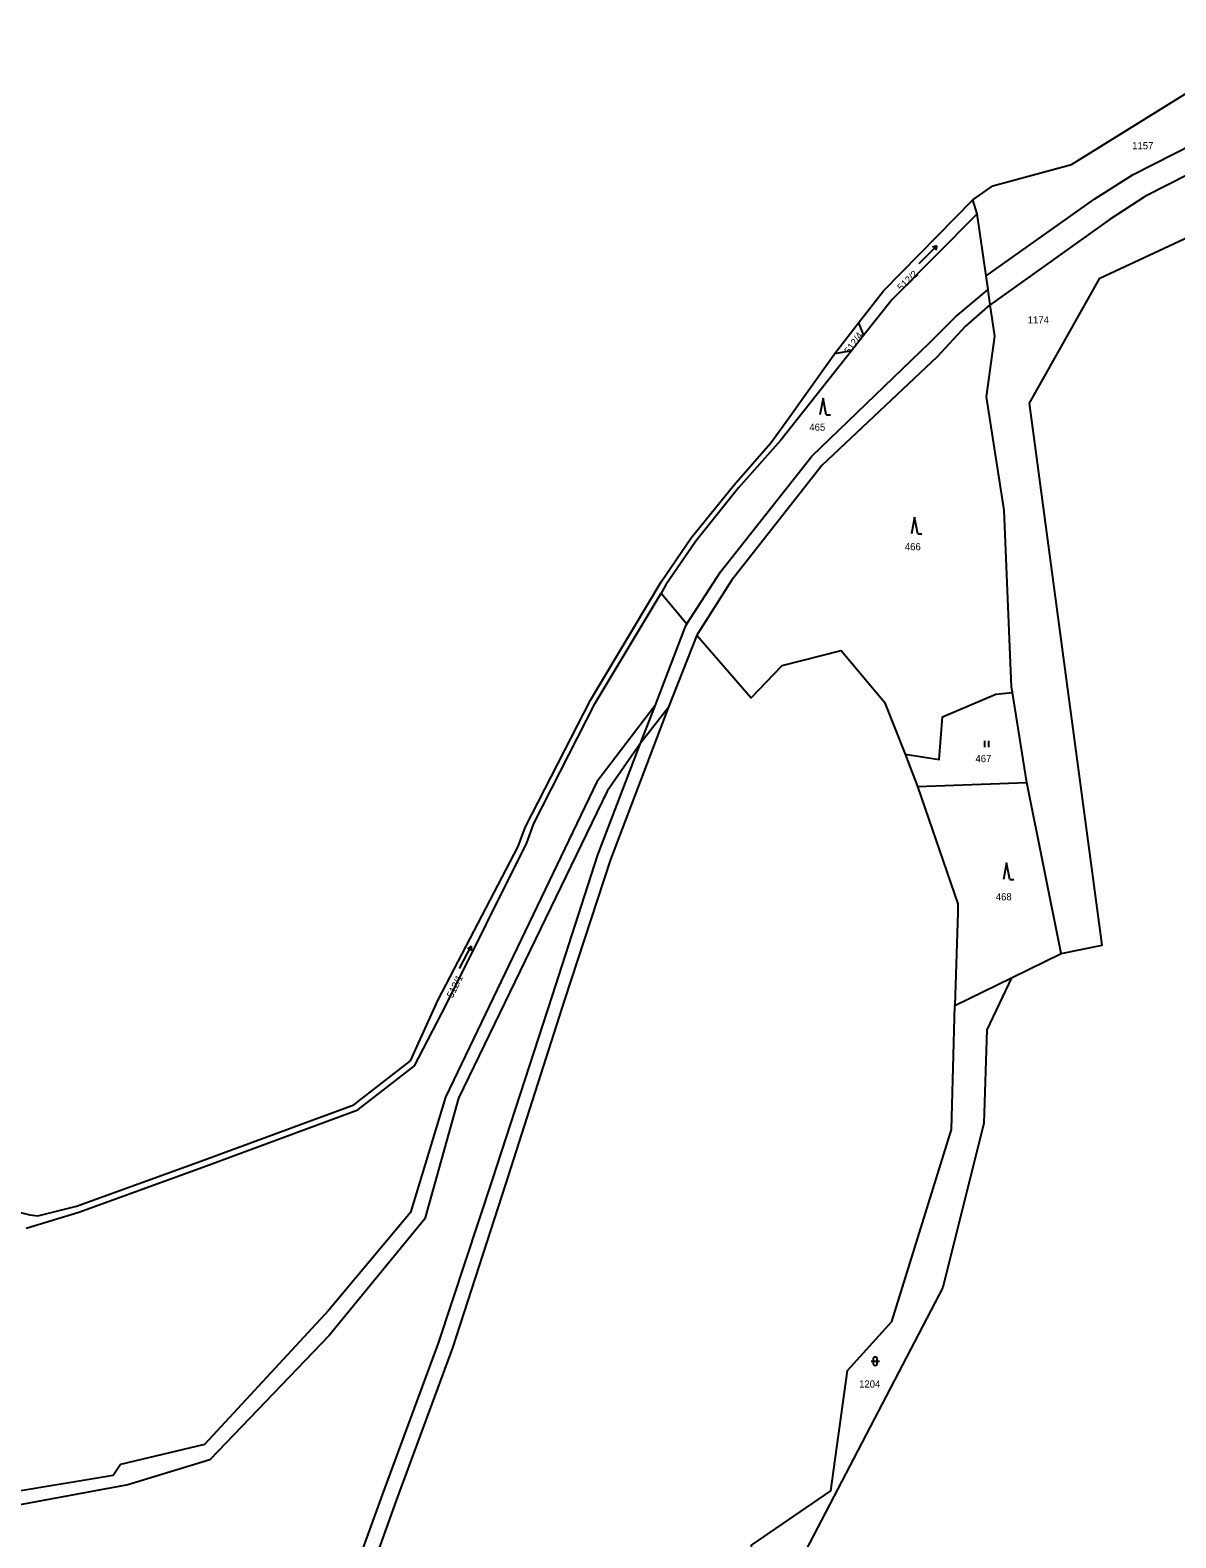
# Model space of a CAD drawing. Extents: x -520431 to -517205, y -1075927 to -1074013.
# Drawn here: x -519035.6 to -518762.1, y -1074599.9 to -1074239.9 of the extents above; entities that cross this region are included whole.
import ezdxf

# ---------------------------------------------------------------- set-up
doc = ezdxf.new("R2010")
doc.units = 0
for name, color, linetype in [('Hranice parcel', 7, 'Continuous'), ('Parcelní čísla', 7, 'Continuous'), ('Vnitřní kresba', 7, 'Continuous'), ('Značky kultur', 7, 'Continuous')]:
    doc.layers.add(name, color=color, linetype=linetype)

msp = doc.modelspace()

# ---------------------------------------------------------------- linework, layer by layer
at = {"layer": 'Hranice parcel'}
for p, q in [((-518805.81, -1074277.13), (-518787, -1074272.03)), ((-518810.55, -1074280.41), (-518805.81, -1074277.13)), ((-518831.89, -1074302.13), (-518810.55, -1074280.41)), ((-518809.56, -1074283.75), (-518810.55, -1074280.41)), ((-518809.56, -1074283.75), (-518829.85, -1074304.23)), ((-518807.42, -1074298.56), (-518809.56, -1074283.75)), ((-518806.94, -1074301.88), (-518807.42, -1074298.56)), ((-518837.84, -1074309.79), (-518831.89, -1074302.13)), ((-518829.85, -1074304.23), (-518836.66, -1074312.86)), ((-518806.41, -1074305.5), (-518806.42, -1074305.43)), ((-518843.61, -1074317.21), (-518837.84, -1074309.79)), ((-518837.84, -1074309.79), (-518836.66, -1074312.86)), ((-518836.66, -1074312.86), (-518839.52, -1074316.48)), ((-518839.52, -1074316.48), (-518856.38, -1074337.85)), ((-518855.25, -1074333.52), (-518843.77, -1074317.42)), ((-518843.77, -1074317.42), (-518843.61, -1074317.21)), ((-518839.52, -1074316.48), (-518843.61, -1074317.21)), ((-518877.83, -1074361.14), (-518867.52, -1074348.45)), ((-518884.99, -1074371.64), (-518877.83, -1074361.14)), ((-518878.84, -1074381.66), (-518870.83, -1074369.29)), ((-518901.86, -1074399.9), (-518884.99, -1074371.64)), ((-518883.83, -1074372.33), (-518885.01, -1074374.31)), ((-518900.71, -1074400.59), (-518885.01, -1074374.31)), ((-518885.01, -1074374.31), (-518878.84, -1074381.66)), ((-518876.49, -1074384.37), (-518883.29, -1074401.72)), ((-518801.13, -1074398.07), (-518801.34, -1074396.78)), ((-518797.69, -1074419.55), (-518801.13, -1074398.07)), ((-518826.75, -1074412.75), (-518823.76, -1074420.48)), ((-518823.76, -1074420.48), (-518797.69, -1074419.55)), ((-518789.46, -1074460.36), (-518797.69, -1074419.55)), ((-518801.36, -1074466.16), (-518789.46, -1074460.36)), ((-518814.9, -1074472.76), (-518801.36, -1074466.16)), ((-518958.35, -1074496.5), (-518944.83, -1074485.99)), ((-519036.6, -1074525.93), (-519024.03, -1074522.12))]:
    msp.add_line(p, q, dxfattribs=at)
for points in [[(-518807.42, -1074298.56), (-518781.44, -1074280.23), (-518772.33, -1074274.36), (-518709.23, -1074242.3), (-518702.57, -1074239.93)], [(-518787, -1074272.03), (-518741.51, -1074243.77), (-518736.66, -1074241.32)], [(-518700.72, -1074245.65), (-518706.84, -1074247.83), (-518769.32, -1074279.56), (-518778.06, -1074285.2), (-518806.41, -1074305.5)], [(-518789.46, -1074460.36), (-518779.66, -1074458.38), (-518797.01, -1074329.01), (-518780.23, -1074299.11), (-518692.92, -1074258.36)], [(-518870.83, -1074369.29), (-518848.97, -1074341.65), (-518820.87, -1074314.47), (-518814.74, -1074308.37), (-518806.94, -1074301.88)], [(-518806.42, -1074305.43), (-518806.83, -1074302.67), (-518806.94, -1074301.88)], [(-518806.42, -1074305.43), (-518812.29, -1074310.63), (-518819.06, -1074317.91), (-518846.65, -1074343.88), (-518868.19, -1074371.33), (-518876.49, -1074384.37)], [(-518801.34, -1074396.78), (-518803.09, -1074354.54), (-518807.3, -1074327.49), (-518805.3, -1074312.99), (-518806.41, -1074305.5)], [(-518867.52, -1074348.45), (-518858.79, -1074338.49), (-518856.9, -1074335.84), (-518855.25, -1074333.52)], [(-518856.38, -1074337.85), (-518866.53, -1074349.23), (-518876.71, -1074361.9), (-518883.83, -1074372.33)], [(-518878.84, -1074381.66), (-518879.24, -1074382.29), (-518886.51, -1074401.23)], [(-518876.49, -1074384.37), (-518863.52, -1074399.32), (-518856.08, -1074391.65), (-518841.97, -1074388.02), (-518831.68, -1074400.38), (-518826.75, -1074412.75)], [(-518826.75, -1074412.75), (-518818.58, -1074414.04), (-518817.81, -1074403.85), (-518805.11, -1074398.46), (-518801.13, -1074398.07)], [(-518886.51, -1074401.23), (-518900.35, -1074419.35), (-518936.48, -1074494.71), (-518944.81, -1074522.23), (-518964.42, -1074545.59), (-518994.02, -1074577.6), (-519014.03, -1074582.35), (-519015.8, -1074585), (-519041.66, -1074589.31), (-519072.61, -1074604.97), (-519097.89, -1074612.94), (-519127.28, -1074634.12), (-519171.73, -1074659.2), (-519290.83, -1074723.35), (-519316.3, -1074741.22), (-519349.48, -1074768.81), (-519373.36, -1074775.06), (-519417.58, -1074772.1), (-519455.35, -1074775.46)], [(-519024.03, -1074522.12), (-518994.36, -1074511.41), (-518957.4, -1074497.73), (-518943.87, -1074487.22), (-518936.4, -1074472.82), (-518917.02, -1074433.97), (-518915.36, -1074429.36), (-518900.71, -1074400.59)], [(-518919.09, -1074434.81), (-518917.42, -1074430.27), (-518901.86, -1074399.9)], [(-518883.29, -1074401.72), (-518890.04, -1074410.39), (-518897.9, -1074421.6), (-518933.37, -1074494.89), (-518941.4, -1074523.76), (-518964.23, -1074551.55), (-518992.68, -1074581.23), (-519012.26, -1074587.2), (-519040.61, -1074592.47)], [(-518823.76, -1074420.48), (-518814.18, -1074448.48), (-518814.16, -1074450.56), (-518814.9, -1074472.76)], [(-518944.83, -1074485.99), (-518938.18, -1074471.43), (-518919.09, -1074434.81)], [(-518801.36, -1074466.16), (-518807.22, -1074478.57), (-518807.97, -1074500.86), (-518817.74, -1074540.12), (-518856.3, -1074614.09), (-518857.09, -1074629.8), (-518854.54, -1074645.37), (-518845, -1074648.92)], [(-518860.87, -1074659.24), (-518863.43, -1074601.67), (-518844.5, -1074588.65), (-518840.53, -1074559.95), (-518829.89, -1074548.2), (-518815.63, -1074502.38), (-518814.9, -1074472.76)], [(-519024.56, -1074520.67), (-518994.9, -1074509.93), (-518958.35, -1074496.5)], [(-519044, -1074520.8), (-519036.29, -1074522.63), (-519035.72, -1074522.77), (-519033.79, -1074523.03), (-519024.56, -1074520.67)]]:
    msp.add_lwpolyline(points, dxfattribs=at)
at = {"layer": 'Vnitřní kresba'}
for p, q in [((-518886.51, -1074401.23), (-518890.04, -1074410.39)), ((-518883.29, -1074401.72), (-518897.1, -1074437.93)), ((-518890.04, -1074410.39), (-518900.2, -1074436.82)), ((-518900.2, -1074436.82), (-518911.01, -1074470.39)), ((-518897.1, -1074437.93), (-518908.03, -1074471.43)), ((-518911.01, -1074470.39), (-518925.33, -1074514.44)), ((-518908.03, -1074471.43), (-518922.13, -1074515.45)), ((-518925.33, -1074514.44), (-518938.2, -1074553.4)), ((-518922.13, -1074515.45), (-518934.82, -1074554.5)), ((-518938.2, -1074553.4), (-518951.54, -1074589.65)), ((-518934.82, -1074554.5), (-518948.23, -1074590.97)), ((-518951.54, -1074589.65), (-518968.46, -1074635.79)), ((-518948.23, -1074590.97), (-518964.95, -1074637.39))]:
    msp.add_line(p, q, dxfattribs=at)
at = {"layer": 'Značky kultur'}
for p, q in [((-518823.42, -1074295.64), (-518819.18, -1074291.39)), ((-518819.18, -1074291.39), (-518820.23, -1074291.73)), ((-518819.18, -1074291.39), (-518819.52, -1074292.44)), ((-518846.34, -1074327.78), (-518847.09, -1074331.78)), ((-518845.59, -1074331.78), (-518846.34, -1074327.78)), ((-518845.59, -1074331.78), (-518844.59, -1074331.78)), ((-518824.48, -1074356.17), (-518825.23, -1074360.17)), ((-518823.73, -1074360.17), (-518824.48, -1074356.17)), ((-518823.73, -1074360.17), (-518822.73, -1074360.17)), ((-518807.74, -1074411.11), (-518807.74, -1074409.61)), ((-518806.74, -1074411.11), (-518806.74, -1074409.61)), ((-518802.52, -1074438.71), (-518803.27, -1074442.71)), ((-518801.77, -1074442.71), (-518802.52, -1074438.71)), ((-518801.77, -1074442.71), (-518800.77, -1074442.71)), ((-518933.15, -1074463.92), (-518930.34, -1074458.62)), ((-518930.34, -1074458.62), (-518931.24, -1074459.25)), ((-518930.34, -1074458.62), (-518930.35, -1074459.72)), ((-518834.88, -1074557.72), (-518832.88, -1074557.72)), ((-518834.38, -1074557.22), (-518834.38, -1074558.22)), ((-518833.38, -1074558.22), (-518833.38, -1074557.22))]:
    msp.add_line(p, q, dxfattribs=at)
for centre, start, end in [((-518833.88, -1074557.22), 0, 180), ((-518833.88, -1074558.22), 180, 359.9879)]:
    msp.add_arc(centre, 0.5, start, end, dxfattribs=at)

# ---------------------------------------------------------------- texts
at = {"layer": 'Parcelní čísla'}
for s, p in [('1157', (-518772.53, -1074268.36)), ('1174', (-518797.46, -1074309.95)), ('466', (-518826.8, -1074364.09)), ('467', (-518809.95, -1074414.69)), ('468', (-518805.1, -1074447.68)), ('1204', (-518837.72, -1074564))]:
    msp.add_text(s, height=1.7, dxfattribs=at).set_placement(p)
for s, rotation, p in [('512/2', 44, (-518827.62, -1074302.3)), ('512/4', 54, (-518840.04, -1074317.42)), ('465', 1, (-518849.59, -1074335.6)), ('512/1', 64, (-518934.73, -1074471.14))]:
    msp.add_text(s, height=1.7, rotation=rotation, dxfattribs=at).set_placement(p)

doc.saveas('drawing.dxf')
